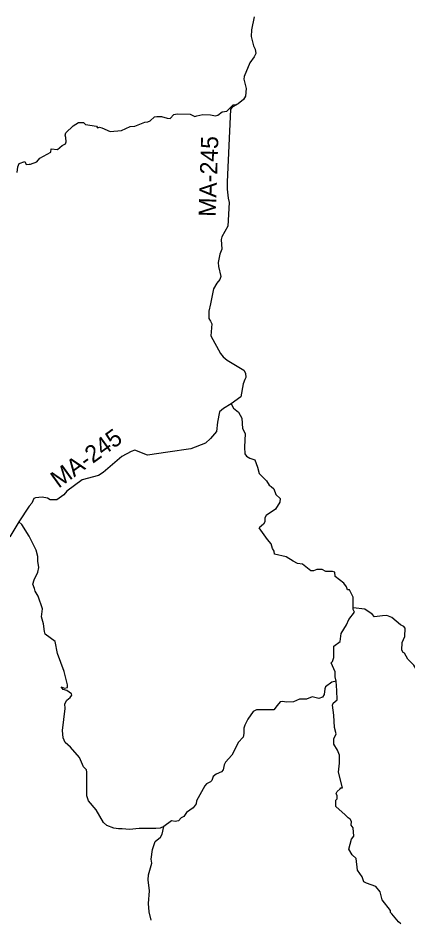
# Model space of a CAD drawing. Extents: x 332 to 501, y 9447 to 9559.
# Drawn here: x 475.76 to 484.34, y 9460.15 to 9479.97 of the extents above; entities that cross this region are included whole.
import ezdxf

# ---------------------------------------------------------------- set-up
doc = ezdxf.new("R2010")
doc.units = 0
for name, color, linetype in [('Level 31', 7, 'Continuous'), ('Level 4', 7, 'Continuous'), ('Level 5', 7, 'Continuous'), ('Level 6', 7, 'Continuous')]:
    doc.layers.add(name, color=color, linetype=linetype)

msp = doc.modelspace()

# ---------------------------------------------------------------- linework, layer by layer
at = {"layer": 'Level 4'}
for points in [[(480.9663, 9480), (480.906, 9479.7106), (480.899, 9479.5635), (480.9515, 9479.3603), (480.9865, 9479.2832), (481.0005, 9479.1921), (480.969, 9479.115), (480.8745, 9478.9819), (480.7449, 9478.6806), (480.7379, 9478.6226), (480.7904, 9478.4194), (480.7729, 9478.2477), (480.7344, 9478.1776), (480.611, 9478.0848)], [(480.5807, 9478.0667), (480.4761, 9477.9996), (480.442, 9477.9595), (480.3673, 9476.3638), (480.3673, 9476.2032), (480.3929, 9476)], [(480.611, 9478.0848), (480.5807, 9478.0667)], [(480.3929, 9476), (480.4117, 9475.9059), (480.3878, 9475.383), (480.2512, 9475.1517), (480.2375, 9475.0867), (480.2512, 9474.8749), (480.2068, 9474.7689), (480.1692, 9474.5799), (480.1761, 9474.4911), (480.2307, 9474.2758), (480.2102, 9474.2074), (480.1419, 9474.1289), (480.0702, 9474.0024), (479.9999, 9473.6691)], [(479.9999, 9473.6691), (479.9677, 9473.5103), (479.9677, 9473.3507), (479.9999, 9473.288)], [(479.9999, 9473.288), (480.0292, 9473.2311), (480.0087, 9472.9646), (480.2273, 9472.5729), (480.2819, 9472.5012), (480.3673, 9472.4294), (480.7362, 9472.2107), (480.7772, 9472.1389), (480.7806, 9472.0467), (480.7627, 9472)], [(480.7627, 9472), (480.7259, 9471.9042), (480.6713, 9471.6205), (480.4589, 9471.4684)], [(480.4589, 9471.4684), (480.2922, 9471.3642), (480.2, 9471.287), (480.1556, 9471.0648), (480.1351, 9470.8564), (479.9999, 9470.7043)], [(479.9999, 9470.7043), (479.8926, 9470.6001), (479.5715, 9470.4737), (479.0626, 9470.4036)], [(479.0626, 9470.4036), (478.6132, 9470.3318), (478.3365, 9470.4412), (478.2512, 9470.4173), (478.0496, 9470.3079), (477.6378, 9469.9501), (477.5319, 9469.8886), (477.1733, 9469.7895), (476.8317, 9469.5434), (476.7703, 9469.4614), (476.6097, 9469.3521), (476.4663, 9469.3487), (476.4082, 9469.3828), (476.2901, 9469.4078), (476.1432, 9469.3941), (476.1057, 9469.377), (476.0613, 9469.2779), (475.9999, 9469.2068)], [(475.9999, 9469.2068), (475.7732, 9468.8629)], [(475.7732, 9468.8629), (475.5797, 9468.5343), (475.4294, 9468.4933), (475.2293, 9468.4938)]]:
    msp.add_lwpolyline(points, dxfattribs=at)
at = {"layer": 'Level 5'}
for points in [[(480, 9477.837), (480.113, 9477.82), (480.163, 9477.835), (480.262, 9477.904), (480.363, 9477.923), (480.503, 9478.057), (480.5807, 9478.0667)], [(478.2341, 9477.579), (478.337, 9477.591), (478.556, 9477.675), (478.619, 9477.682), (478.674, 9477.705), (478.7651, 9477.7921), (478.822, 9477.805), (478.923, 9477.804), (479.047, 9477.762), (479.112, 9477.757), (479.195, 9477.846), (479.2651, 9477.861), (479.551, 9477.855), (479.655, 9477.8), (479.7048, 9477.8202)], [(479.7048, 9477.8202), (479.836, 9477.844), (480, 9477.837)], [(476.8088, 9477.336), (476.799, 9477.388), (476.813, 9477.439), (476.971, 9477.594), (477.09, 9477.668), (477.1981, 9477.6707), (477.247, 9477.628), (477.486, 9477.5911), (477.507, 9477.549), (477.557, 9477.5641), (477.605, 9477.552), (477.792, 9477.468), (478.039, 9477.495), (478.133, 9477.5339)], [(478.133, 9477.5339), (478.2341, 9477.579)], [(475.9999, 9476.7506), (476.034, 9476.748), (476.1711, 9476.804), (476.241, 9476.884), (476.482, 9477.012), (476.4852, 9477.0885), (476.625, 9477.078), (476.73, 9477.161), (476.802, 9477.196), (476.819, 9477.241), (476.8088, 9477.336)], [(475.7388, 9476.5687), (475.753, 9476.691), (475.781, 9476.767), (475.9041, 9476.811), (475.934, 9476.747), (475.9999, 9476.7506)], [(480.4589, 9471.4684), (480.5101, 9471.37), (480.6209, 9471.2789), (480.6965, 9471.1525), (480.7122, 9470.9234), (480.7677, 9470.8133), (480.752, 9470.5076), (480.7634, 9470.3639), (480.7975, 9470.3126), (480.8686, 9470.2642), (480.9782, 9470.2329), (481.0394, 9470.0709)], [(481.0394, 9470.0709), (481.0798, 9469.9333), (481.2365, 9469.7703), (481.2952, 9469.67), (481.3439, 9469.6456), (481.4014, 9469.588), (481.448, 9469.4687), (481.5399, 9469.3758), (481.5363, 9469.2989), (481.4338, 9469.1412), (481.2297, 9469.0049), (481.2027, 9468.9523), (481.1995, 9468.8664)], [(475.9999, 9468.5511), (475.842, 9468.807), (475.7732, 9468.8629)], [(481.1995, 9468.8664), (481.1728, 9468.8143), (481.078, 9468.7309)], [(481.261, 9468.4766), (481.078, 9468.7309)], [(476.1923, 9468), (476.195, 9468.101), (476.161, 9468.239), (475.9999, 9468.5511)], [(481.8245, 9468), (481.6688, 9468.0885), (481.4186, 9468.1486), (481.4086, 9468.2187), (481.3686, 9468.2788), (481.3385, 9468.3789), (481.261, 9468.4766)], [(476.1174, 9467.3904), (476.085, 9467.492), (476.111, 9467.585), (476.195, 9467.755), (476.214, 9467.856), (476.1923, 9468)], [(482.5488, 9467.7722), (482.4663, 9467.8122), (482.3463, 9467.8122), (482.2762, 9467.7822), (482.2162, 9467.7822), (482.036, 9467.9324), (481.9258, 9467.9424), (481.8245, 9468)], [(483.1469, 9466.9689), (483.1469, 9467.2014), (483.0668, 9467.3616), (483.0268, 9467.3616), (483.0068, 9467.4317), (482.9467, 9467.5118), (482.7566, 9467.662), (482.7467, 9467.7521), (482.6965, 9467.7722), (482.5488, 9467.7722)], [(476.6302, 9465.9627), (476.578, 9466.222), (476.359, 9466.387), (476.339, 9466.442), (476.322, 9466.615), (476.272, 9466.766), (476.297, 9466.947), (476.202, 9467.228), (476.136, 9467.3321), (476.1174, 9467.3904)], [(483.0067, 9466.5929), (483.0568, 9466.7107), (483.1769, 9466.8709), (483.1469, 9466.931), (483.1469, 9466.9689)], [(483.5728, 9466.8248), (483.4059, 9466.9382), (483.1469, 9466.9689)], [(482.7754, 9465.3527), (482.7566, 9465.443), (482.7566, 9465.5532), (482.6665, 9465.7535), (482.6965, 9465.7835), (482.7265, 9465.8736), (482.7265, 9466.124), (482.8667, 9466.2241), (482.8867, 9466.4003), (483.0067, 9466.5929)], [(476.774, 9465.562), (476.6302, 9465.9627)], [(476.7953, 9464.7481), (476.79, 9464.85), (476.837, 9464.928), (476.911, 9464.993), (476.941, 9465.045), (476.934, 9465.071), (476.831, 9465.141), (476.753, 9465.167), (476.712, 9465.228), (476.779, 9465.198), (476.8511, 9465.212), (476.85, 9465.266), (476.774, 9465.562)], [(482.7754, 9465.3527), (482.682, 9465.331), (482.543, 9465.222), (482.523, 9465.179), (482.513, 9465.059), (482.476, 9464.995), (482.394, 9464.968), (482.248, 9465.002), (482.118, 9464.957), (481.97, 9464.95), (481.837, 9464.8921), (481.686, 9464.884), (481.587, 9464.904), (481.539, 9464.894), (481.4766, 9464.8157)], [(482.7934, 9465.1434), (482.7754, 9465.3527)], [(482.7265, 9464), (482.7265, 9464.0812), (482.7766, 9464.1913), (482.7366, 9464.3315), (482.7265, 9464.6019), (482.6965, 9464.8222), (482.7064, 9464.8622), (482.7966, 9464.9424), (482.7934, 9465.1434)], [(476.7935, 9464), (476.755, 9464.101), (476.739, 9464.259), (476.7953, 9464.7481)], [(481.4766, 9464.8157), (481.397, 9464.721), (481.015, 9464.72), (480.946, 9464.682), (480.826, 9464.514), (480.762, 9464.38), (480.741, 9464.316), (480.742, 9464.197), (480.725, 9464.118), (480.6134, 9464)], [(477.2761, 9463.3439), (477.269, 9463.396), (477.202, 9463.459), (477.112, 9463.666), (476.914, 9463.894), (476.7935, 9464)], [(480.6134, 9464), (480.5198, 9463.7988)], [(482.8466, 9463.6454), (482.8466, 9463.7207), (482.8066, 9463.8308), (482.7265, 9463.961), (482.7265, 9464)], [(480.5198, 9463.7988), (480.471, 9463.717), (480.333, 9463.567), (480.3039, 9463.508), (480.282, 9463.395), (480.2481, 9463.352), (480.127, 9463.299), (480.065, 9463.251), (480.033, 9463.157), (479.9999, 9463.134)], [(482.8266, 9463.3402), (482.8466, 9463.5404)], [(482.8466, 9463.5404), (482.8466, 9463.6454)], [(477.9749, 9462.0938), (477.874, 9462.108), (477.717, 9462.167), (477.644, 9462.237), (477.483, 9462.515), (477.314, 9462.711), (477.276, 9462.819), (477.2761, 9463.3439)], [(482.9167, 9462.9948), (482.8266, 9463.3402)], [(479.9999, 9463.134), (479.917, 9463.088), (479.881, 9463.042), (479.692, 9462.711), (479.686, 9462.648), (479.6205, 9462.5601)], [(483.0368, 9462.3339), (482.9767, 9462.404), (482.7666, 9462.5842), (482.7666, 9462.7244), (482.7966, 9462.7545), (482.7966, 9462.8246), (482.7766, 9462.8746)], [(482.7766, 9462.8746), (482.7966, 9462.9147), (482.8647, 9462.9769)], [(482.8647, 9462.9769), (482.8768, 9462.9948)], [(482.8768, 9462.9948), (482.9167, 9462.9948)], [(479.6205, 9462.5601), (479.473, 9462.453), (479.415, 9462.369), (479.356, 9462.337), (479.3, 9462.2741), (479.227, 9462.256), (479.14, 9462.268), (478.973, 9462.146)], [(483.0851, 9462.305), (483.0368, 9462.3339)], [(483.4416, 9460.8957), (483.3871, 9460.922), (483.347, 9461.0321), (483.247, 9461.1823), (483.2169, 9461.4427), (483.1269, 9461.5228), (483.0568, 9461.643), (483.1169, 9461.8632), (483.1669, 9461.9333), (483.1469, 9462.1136), (483.1068, 9462.1737), (483.1169, 9462.2538), (483.0851, 9462.305)], [(478.0543, 9462.0914), (477.9749, 9462.0938)], [(478.973, 9462.146), (478.894, 9462.109), (478.797, 9462.1), (478.431, 9462.104), (478.22, 9462.078), (478.0543, 9462.0914)], [(478.7249, 9461.6353), (478.782, 9461.812), (478.898, 9461.911), (478.94, 9461.975), (478.973, 9462.146)], [(478.6938, 9460.0801), (478.651, 9460.262), (478.634, 9460.451), (478.659, 9460.725), (478.627, 9460.968), (478.632, 9461.082), (478.706, 9461.334), (478.695, 9461.427), (478.7249, 9461.6353)], [(484, 9460.2223), (483.9775, 9460.251), (483.9775, 9460.2911), (483.7874, 9460.5314), (483.7473, 9460.7017), (483.6473, 9460.8218), (483.4416, 9460.8957)], [(484.1994, 9460), (484.1476, 9460.0407), (484, 9460.2223)]]:
    msp.add_lwpolyline(points, dxfattribs=at)
at = {"layer": 'Level 6'}
for points in [[(483.7945, 9466.7888), (483.623, 9466.77), (483.5728, 9466.8248)], [(484, 9466.7516), (483.896, 9466.8), (483.7945, 9466.7888)], [(484.2529, 9465.9832), (484.224, 9466.0351), (484.231, 9466.205), (484.287, 9466.335), (484.3, 9466.519), (484.267, 9466.559), (484.198, 9466.596), (484, 9466.7516)], [(485.5351, 9465.32), (485.464, 9465.311), (485.23, 9465.379), (484.843, 9465.376), (484.718, 9465.404), (484.642, 9465.451), (484.576, 9465.519), (484.542, 9465.617), (484.489, 9465.702), (484.359, 9465.832), (484.283, 9465.965), (484.2529, 9465.9832)]]:
    msp.add_lwpolyline(points, dxfattribs=at)

# ---------------------------------------------------------------- texts
at = {"layer": 'Level 31'}
for rotation, p in [(88.10457, (480.1186, 9475.5856)), (35.93026, (476.6512, 9469.5931))]:
    msp.add_text('MA-245', height=0.38, rotation=rotation, dxfattribs=at).set_placement(p)

doc.saveas('drawing.dxf')
